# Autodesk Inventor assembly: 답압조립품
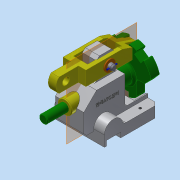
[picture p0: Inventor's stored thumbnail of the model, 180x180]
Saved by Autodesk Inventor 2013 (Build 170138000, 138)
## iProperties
Created: 2016-11
Part Number: 답압조립품
Document SubType Name: Assembly
Designer: dgall
Author: dgall
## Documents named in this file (8)
- C:\Users\dgall\Desktop\461107V1010\답압조립품.iam
- C:\Users\dgall\Desktop\461107V1010\본체.ipt
- C:\Users\dgall\Desktop\461107V1010\부시.ipt
- C:\Users\dgall\Desktop\461107V1010\분할대.ipt
- C:\Users\dgall\Desktop\461107V1010\분할축.ipt
- C:\Users\dgall\Desktop\461107V1010\와셔.ipt
- C:\Users\dgall\Desktop\461107V1010\원통형핀.ipt
- C:\Users\dgall\Desktop\461107V1010\클레비스핀.ipt
